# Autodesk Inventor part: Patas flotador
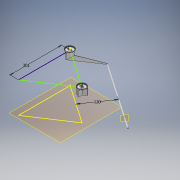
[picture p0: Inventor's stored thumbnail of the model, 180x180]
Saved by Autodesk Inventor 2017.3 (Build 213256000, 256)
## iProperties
Part Number: Patas flotador
Material: Genérico
Document SubType Name: Modeling
Designer: PABLO HERNANDEZ
Density: 1 g/cm^3
Appearance: Valor por defecto
Author: PABLO HERNANDEZ
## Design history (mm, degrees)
sketch "Boceto1"
  geometry: C1 r 16 at (0, 0); 1 further point
  constraints: 1 centre point, 1 coincident
  dimensions: "d0" = 32 diameter of C1
extrude "Extrusión1" new body sketch "Boceto1" distance "d1" = 1; taper "d2" = 0 deg; dims "d93" = 1, "d94" = 0
sketch "Boceto2"
  geometry: C1 r 16 at (0, 0); C2 r 15 at (0, 0); C3 r 14 at (0, 0); 1 further point
  constraints: 3 centre point, 1 coincident
  dimensions: "d3" = 1 radial gap between concentric circles of C1 C2; "d4" = 1 radial gap between concentric circles of C2 C3
extrude "Extrusión2" join sketch "Boceto2" distance "d5" = 3; taper "d6" = 0 deg
sketch "Boceto3"
  geometry: C1 r 15 at (0, 0); C2 r 14 at (0, 0); 1 further point
  constraints: 2 centre point, 1 coincident
  dimensions: "d7" = 1 radial gap between concentric circles of C1 C2; "d123" = 30 diameter of C1
extrude "Extrusión3" join sketch "Boceto3" distance "d8" = 2; taper "d9" = 0 deg
sketch "Boceto4"
  geometry: C1 r 16 at (0, 0); 1 further point
  constraints: 1 centre point, 1 coincident
extrude "Extrusión4" cut sketch "Boceto4" distance "d10" = 0.5; taper "d11" = 0 deg
sketch "Boceto7"
  geometry: L1 (1.5, -15.93)-(1.5, 15.93); L2 (-1.5, -15.93)-(-1.5, 15.93); A1 r 16 centre (0, 0) between (1.5, 15.93) and (-1.5, 15.93); A2 r 16 centre (0, 0) between (-1.5, -15.93) and (1.5, -15.93); 2 further points
  constraints: 4 end point, 4 point on circle, 2 centre point, 1 coincident
extrude "Extrusión7" join sketch "Boceto7" distance "d63" = 25; taper "d64" = 0 deg
fillet "Empalme1" dims "d71" = 2
fillet "Empalme2" dims "d95" = 3
fillet "Empalme3" dims "d96" = 0.5
sketch "Boceto12"
  geometry: C1 r 1.2 at (-6, 0); C2 r 1.2 at (6, 0); 2 further points
  constraints: 2 centre point, 1 coincident
  dimensions: "d104" = 6 distance of point (0, 0) point (-6, 0); "d114" = 2.4 diameter of C1; "d115" = 2.4 diameter of C2
extrude "Extrusión9" cut sketch "Boceto12" stored distance "d116" = 10; taper "d117" = 0 deg
sketch "Boceto13"
  geometry: C1 r 1.2 at (-6, 0) reference; C2 r 1.75 at (-6, 0); C3 r 1.2 at (6, 0) reference; C4 r 1.75 at (6, 0); 1 further point
  constraints: 2 centre point, 2 coincident
  dimensions: "d118" = 3.5 diameter of C2; "d119" = 3.5 diameter of C4
extrude "Extrusión10" join sketch "Boceto13" distance "d120" = 3; taper "d121" = 0 deg
fillet "Empalme4" dims "d122" = 1
sketch "Boceto14"
  geometry: 1 further point
sketch "Boceto15"
  geometry: C1 r 1.2 at (6, 0) reference; C2 r 2.5 at (6, 0); C3 r 1.2 at (-6, 0) reference; C4 r 2.5 at (-6, 0); 1 further point
  constraints: 2 centre point, 2 coincident
  dimensions: "d124" = 5 diameter of C2; "d125" = 5 diameter of C4
extrude "Extrusión11" cut sketch "Boceto15" distance "d126" = 10; taper "d127" = 0 deg
sketch "Boceto16"
  geometry: L1 (0, 0)-(0, -201); L2 (0, -201)-(149.324, -102.291); L3 (0, 0)-(149.324, -102.291); 1 further point
  constraints: 6 end point, 2 coincident, 1 vertical
  dimensions: "d130" = 201 distance of L1.start L1.end
node "Plano de trabajo1"
pattern_linear "Patrón rectangular1" dims "d134" = 181
sketch "Boceto19"
  geometry: L1 (-6, 0)-(6, 0); C1 r 1.2 at (-6, 0) reference; C2 r 1.2 at (6, 0) reference; 1 further point
  constraints: 2 end point, 1 horizontal
pattern_circular "Patrón circular1" dims angle "d136" = -56.53 deg
node "Boceto 3D1"
node "Plano de trabajo4"
sketch "Boceto20"
  geometry: L1 (0, 0)-(149.324, -102.291) reference; L2 (0, 145.456)-(257.383, -30.859); L3 (0, 0)-(0, -201) reference; L4 (0, -201)-(149.324, -102.291) reference; 3 further points
  constraints: 4 point on line, 2 end point, 1 parallel
  dimensions: "d139" = 120 distance between parallel lines of L1 L2
node "Plano de trabajo5"
sketch "Boceto21"
  geometry: C1 r 2 at (0, 0); 1 further point
  constraints: 1 centre point
  dimensions: "d140" = 4 diameter of C1
extrude "Extrusión12" join sketch "Boceto21" stored distance "d141" = 10; taper "d142" = 0 deg
sketch "Boceto22"
  geometry: L1 (0, 0)-(0, -201) reference; L2 (0, -201)-(149.324, -102.291) reference; 1 further point
sketch "Boceto23"
  geometry: 1 further point
feature "Solevación1" dims "d143" = 0, "d144" = 90 deg, "d145" = 0, "d146" = 90 deg
  node "Aristas1"
  node "Aristas2"
sketch "Boceto24"
  geometry: C1 r 2 at (0, 0); 1 further point
  constraints: 1 centre point
extrude "Extrusión13" join sketch "Boceto24" stored distance "d147" = 10; taper "d148" = 0 deg
node "Sólido1"
other parameters: "sa_0" = 4
